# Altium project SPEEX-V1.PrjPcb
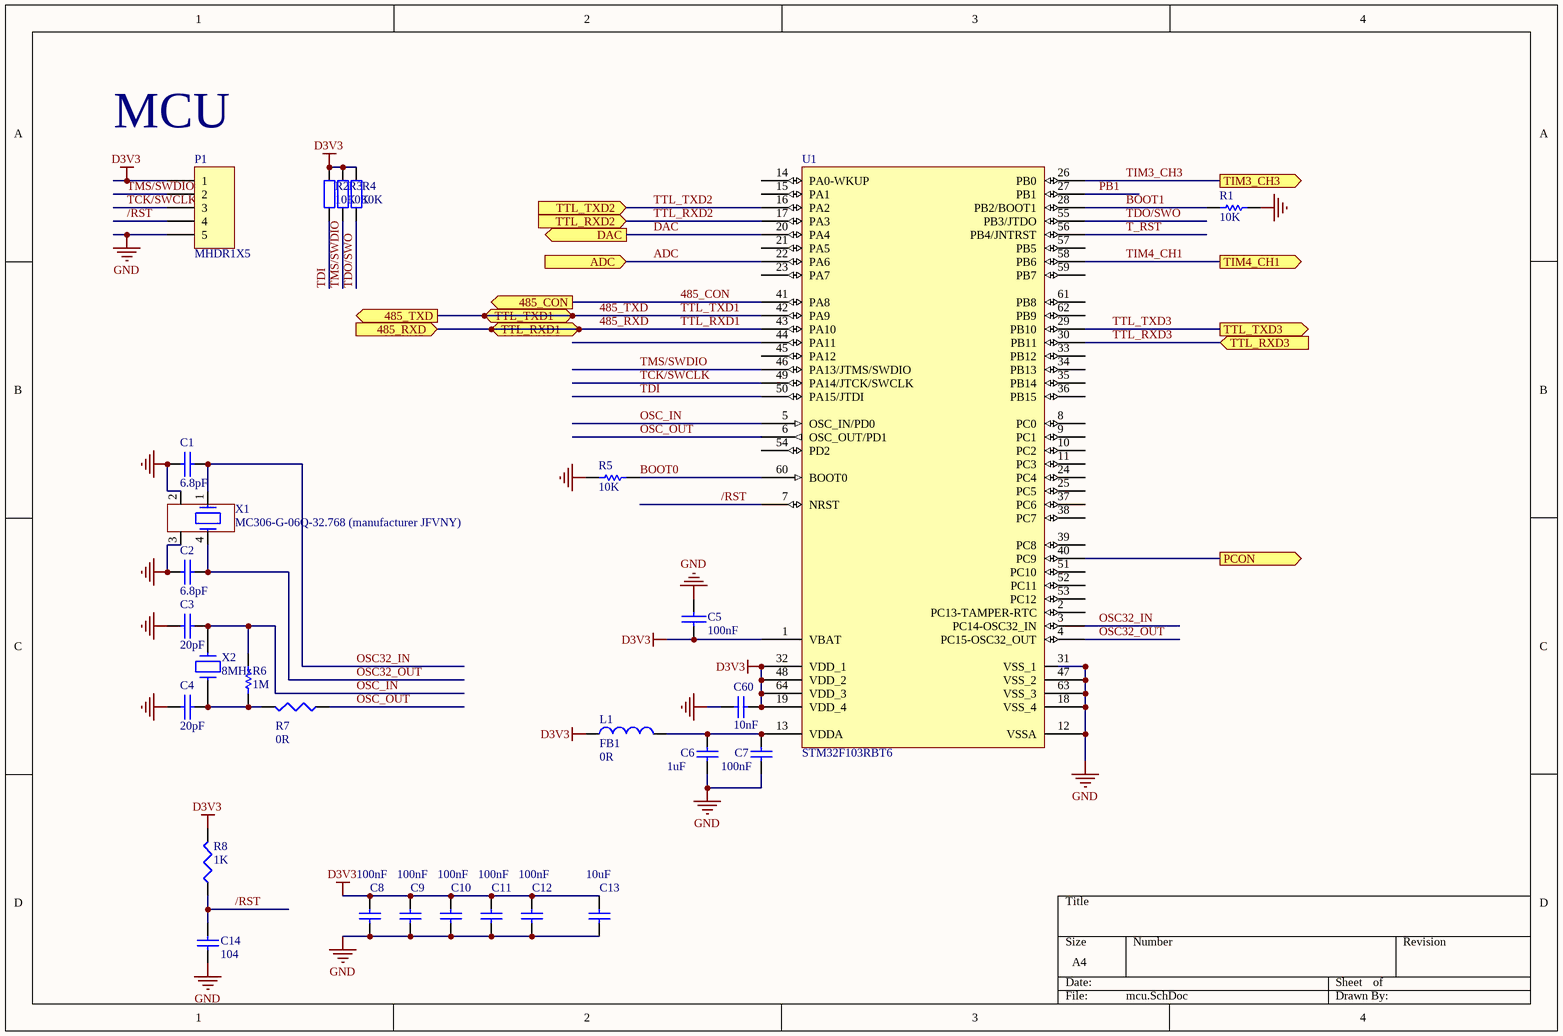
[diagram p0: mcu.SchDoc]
4 sheets, 127 parts. Net scope: flat (ports and power ports of the same name join across sheets).
Board file: SPEEX-V1.PcbDoc
Sheets:
  mcu.SchDoc
  audio_inout.SchDoc
  rs232_485.SchDoc
  power.SchDoc

## Sheet mcu.SchDoc
size A4

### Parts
C1  6.8pF  [C-0603]
C2  6.8pF  [C-0603]
C3  20pF  [C-0603]
C4  20pF  [C-0603]
C5  100nF  [C-0603]
C6  1uF  [C-0603]
C7  100nF  [C-0603]
C8  100nF  [C-0603]
C9  100nF  [C-0603]
C10  100nF  [C-0603]
C11  100nF  [C-0603]
C12  100nF  [C-0603]
C13  10uF  [C-0603]
C14  104  [C-0603]
C60  10nF  [C0603]
L1  FB1  value 0R  [R-0805]
P1  MHDR1X5  [HDR1X5]
R1  10K  [R0603]
R2  10K  [R-0603]
R3  10K  [R-0603]
R4  10K  [R-0603]
R5  10K  [R-0603]
R6  1M  [R-0603]
R7  0R  [R-0603]
R8  1K  [R-0603]
U1  STM32F103RBT6  [LQFP64_N]
X1  MC306-G-06Q-32.768 (manufacturer JFVNY)  [32.768K-MC146]
X2  8MHz  [XTAL-CJ]

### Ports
485_CON (out), 485_RXD (in), 485_TXD (out), ADC (in), DAC (out), PCON (out), TIM3_CH3 (out), TIM4_CH1 (out), TTL_RXD1 (in), TTL_RXD2 (in), TTL_RXD3 (in), TTL_TXD1 (out), TTL_TXD2 (in), TTL_TXD3 (out)

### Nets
D3V3: C5.2 C8.2 C9.2 C10.2 C11.2 C12.2 C13.2 C60.2 L1.1 P1.1 R2.1 R3.1 R4.1 R8.2 U1.1(VBAT) U1.19(VDD_4) U1.32(VDD_1) U1.48(VDD_2) U1.64(VDD_3)
GND: C1.2 C2.2 C3.2 C4.2 C5.1 C6.1 C7.1 C8.1 C9.1 C10.1 C11.1 C12.1 C13.1 C14.1 C60.1 P1.5 R1.2 R5.2 U1.12(VSSA) U1.18(VSS_4) U1.31(VSS_1) U1.47(VSS_2) U1.63(VSS_3) X1.2 X1.3
485_CON: U1.41(PA8) ; port 485_CON
485_RXD: U1.43(PA10) ; port TTL_RXD1, port 485_RXD  [also labelled TTL_RXD1]
485_TXD: U1.42(PA9) ; port TTL_TXD1, port 485_TXD  [also labelled TTL_TXD1]
/RST: C14.2 P1.4 R8.1 U1.7(NRST)
ADC: U1.22(PA6) ; port ADC
BOOT0: R5.1 U1.60(BOOT0)
BOOT1: R1.1 U1.28(PB2/BOOT1)
DAC: U1.20(PA4) ; port DAC
OSC32_IN: C1.1 U1.3(PC14-OSC32_IN) X1.1
OSC32_OUT: C2.1 U1.4(PC15-OSC32_OUT) X1.4
OSC_IN: C3.1 R6.2 U1.5(OSC_IN/PD0) X2.1
OSC_OUT: R7.1 U1.6(OSC_OUT/PD1)
PB1: U1.27(PB1)
PCON: U1.40(PC9) ; port PCON
T_RST: U1.56(PB4/JNTRST)
TCK/SWCLK: P1.3 U1.49(PA14/JTCK/SWCLK)
TDI: R2.2 U1.50(PA15/JTDI)
TDO/SWO: R4.2 U1.55(PB3/JTDO)
TIM3_CH3: U1.26(PB0) ; port TIM3_CH3
TIM4_CH1: U1.58(PB6) ; port TIM4_CH1
TMS/SWDIO: P1.2 R3.2 U1.46(PA13/JTMS/SWDIO)
TTL_RXD2: U1.17(PA3) ; port TTL_RXD2
TTL_RXD3: U1.30(PB11) ; port TTL_RXD3
TTL_TXD2: U1.16(PA2) ; port TTL_TXD2
TTL_TXD3: U1.29(PB10) ; port TTL_TXD3
NetC4_1: C4.1 R6.1 R7.2 X2.2
NetC6_2: C6.2 C7.2 L1.2 U1.13(VDDA)

Not connected (* = marked no-connect by the designer): U1 2(PC13-TAMPER-RTC) 8(PC0) 9(PC1) 10(PC2) 11(PC3) 14(PA0-WKUP) 15(PA1) 21(PA5) 23(PA7) 24(PC4) 25(PC5) 33(PB12) 34(PB13) 35(PB14) 36(PB15) 37(PC6) 38(PC7) 39(PC8) 44(PA11) 45(PA12) 51(PC10) 52(PC11) 53(PC12) 54(PD2) 57(PB5) 59(PB7) 61(PB8) 62(PB9)

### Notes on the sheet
- (near P1) MCU

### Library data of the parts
C1-C5 = CAP: Capacitor
C6-C14 = Cap: Capacitor; Value: 100pF
C60 = Cap: Capacitor
L1 = Inductor: Code_IEC: 1005
P1 = MHDR1X5: Header, 5-Pin
R1 R5 R6 = res1: Resistor; Value: 1K
R2-R4 = RES
R7 = Res3: Resistor; Value: 1K
R8 = Res3: Resistor
U1 = STM32F103RBT6: STM32 ARM-based 32-bit MCU with 128 Kbytes Flash, 64-pin LQFP, Industrial Temperature
X1 = MC306
X2 = CRYSTAL

## Sheet audio_inout.SchDoc
size A4
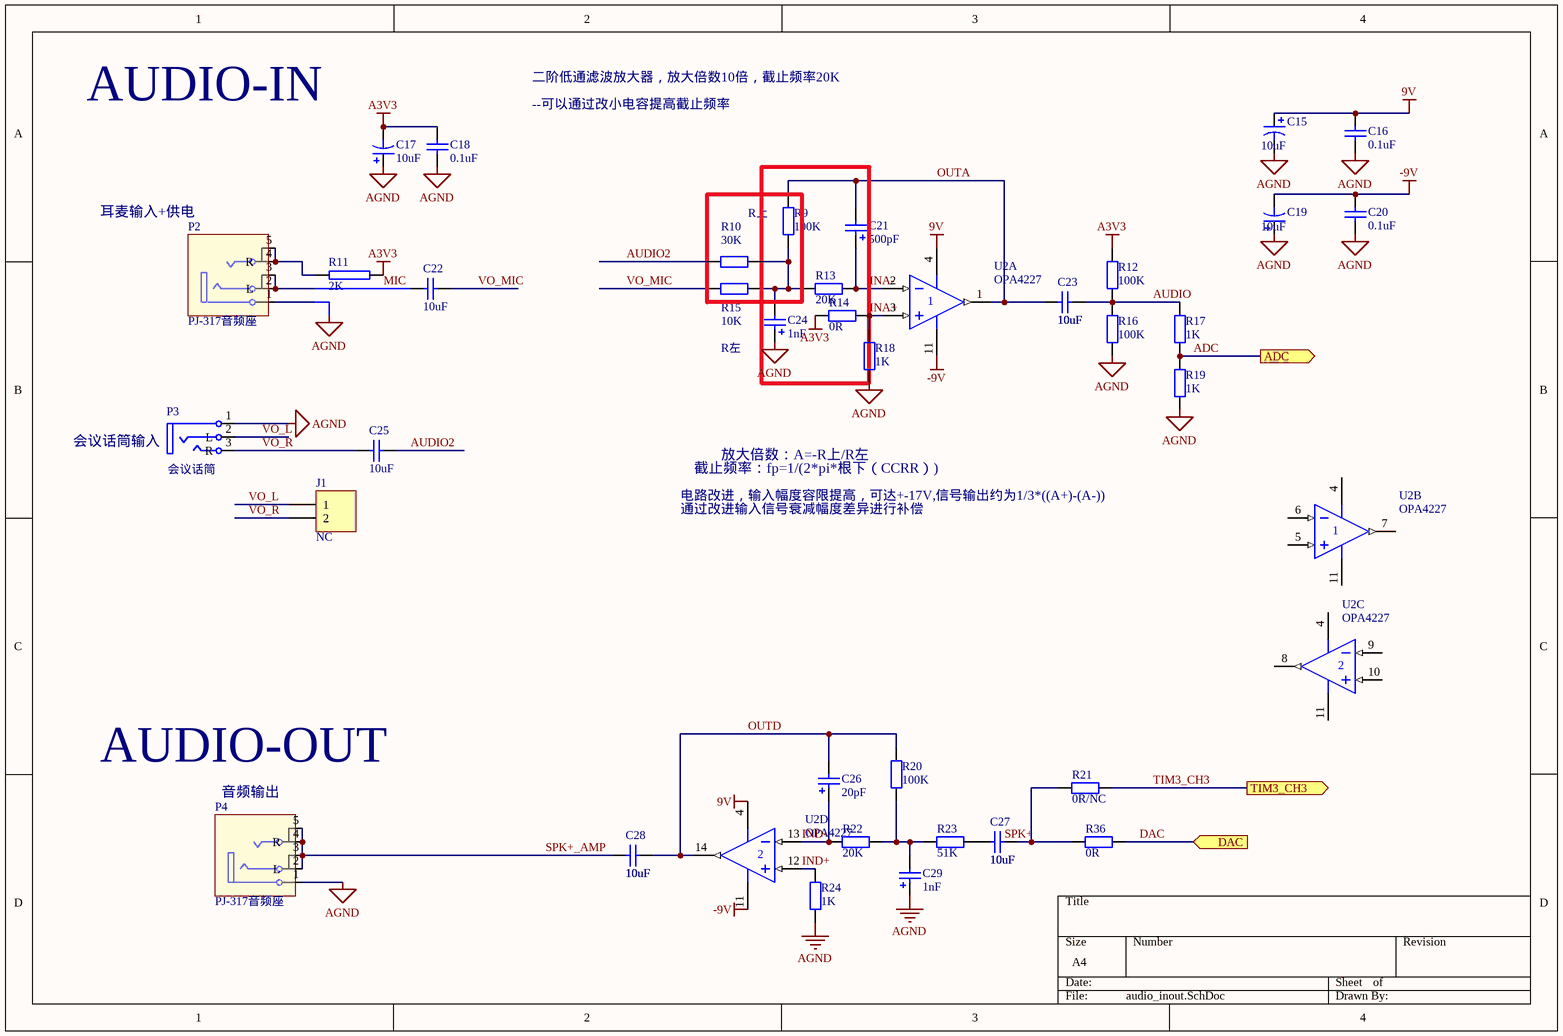
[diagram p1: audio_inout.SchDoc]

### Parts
C15  10uF  [C-0805]
C16  0.1uF  [C-0603]
C17  10uF  [C0805]
C18  0.1uF  [C-0603]
C19  10uF  [C-0805]
C20  0.1uF  [C-0603]
C21  500pF  [C-0603]
C22  10uF  [C-0603]
C23  10uF  [C-0603]
C24  1nF  [C-0603]
C25  10uF  [C-0603]
C26  20pF  [C-0603]
C27  10uF  [C-0603]
C28  10uF  [C-0603]
C29  1nF  [C-0603]
J1  NC  [CON_PAD2]
P2  PJ-317音频座  [PJ-317]
P3  会议话筒  [PJ-603(A)-2]
P4  PJ-317音频座  [PJ-317]
R9  100K  [R-0603]
R10  30K  [R-0603]
R11  2K  [R-0603]
R12  100K  [R-0603]
R13  20K  [R-0603]
R14  0R  [R-0603]
R15  10K  [R-0603]
R16  100K  [R-0603]
R17  1K  [R-0603]
R18  1K  [R-0603]
R19  1K  [R-0603]
R20  100K  [R-0603]
R21  0R/NC  [R-0603]
R22  20K  [R-0603]
R23  51K  [R-0603]
R24  1K  [R-0603]
R36  0R  [R-0603]
U2  OPA4227  [D014_L]  (parts A,B,C,D of 4)

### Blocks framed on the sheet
R上: R9 R10 R15

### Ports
ADC (out), DAC (in), TIM3_CH3 (out)

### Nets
9V: C15.1 C16.2 U2.4(V+)
-9V: C19.2 C20.2 U2.11(V-)
A3V3: C17.2 C18.2 R11.1 R12.1 R14.1
AGND: C15.2 C16.1 C17.1 C18.1 C19.1 C20.1 C24.1 C29.1 P2.1(S) P3.1(S) P4.1(S) R16.2 R18.2 R19.2 R24.2
ADC: R17.2 R19.1 ; port ADC
AUDIO: C23.1 R12.2 R16.1 R17.1
AUDIO2: C25.2 R10.1
DAC: R36.1 ; port DAC
INA+: R14.2 R18.1 U2.3(IN+)
INA-: C21.1 R13.1 U2.2(IN-)
IND+: R24.1 U2.12(IN+)
IND-: C26.1 R22.1 U2.13(IN-)
MIC: C22.1 P2.2(L) P2.3(L)
OUTA: C21.2 C23.2 R9.2 U2.1(OUT)
OUTD: C26.2 C28.1 R20.2 U2.14(OUT)
SPK+_AMP: C28.2 P4.2(L) P4.3(L) P4.4(R) P4.5(R)
TIM3_CH3: R21.1 ; port TIM3_CH3
VO_L: J1.1 P3.2(L)
VO_MIC: C22.2 R15.1
VO_R: C25.1 J1.2 P3.3(R)
NetC24_2: C24.2 R9.1 R10.2 R13.2 R15.2
NetC27_1: C27.1 R21.2 R36.2
NetC27_2: C27.2 R23.1
NetC29_2: C29.2 R20.1 R22.2 R23.2
NetP2_4: P2.4(R) P2.5(R) R11.2

Not connected (* = marked no-connect by the designer): U2 5(IN+) 6(IN-) 7(OUT) 8(OUT) 9(IN-) 10(IN+)

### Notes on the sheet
- AUDIO-IN
- 二阶低通滤波放大器，放大倍数10倍，截止频率20K
- --可以通过改小电容提高截止频率
- 耳麦输入+供电
- R左
- 会议话筒输入
- 电路改进，输入幅度容限提高，可达+-17V,信号输出约为1/3*((A+)-(A-))
- 通过改进输入信号衰减幅度差异进行补偿
- 截止频率：fp=1/(2*pi*根下（CCRR）)
- 放大倍数：A=-R上/R左
- AUDIO-OUT
- (near P4) 音频输出
- Labels drawn without touching a wire or pin: SPK+

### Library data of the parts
C15 C17 C19 = Cap Pol1: Polarized Capacitor (Radial)
C16 C18 C20 C22 C23 C25 C27 C28 = CAP
C21 C24 C26 C29 = Cap Pol2: Polarized Capacitor (Axial); Value: 100pF
J1 = Header 2: Header, 2-Pin
P2 P4 = PJ-317
P3 = MIC
R9 R10 R12-R24 R36 = RES
R11 = RES2

## Sheet rs232_485.SchDoc
size A4
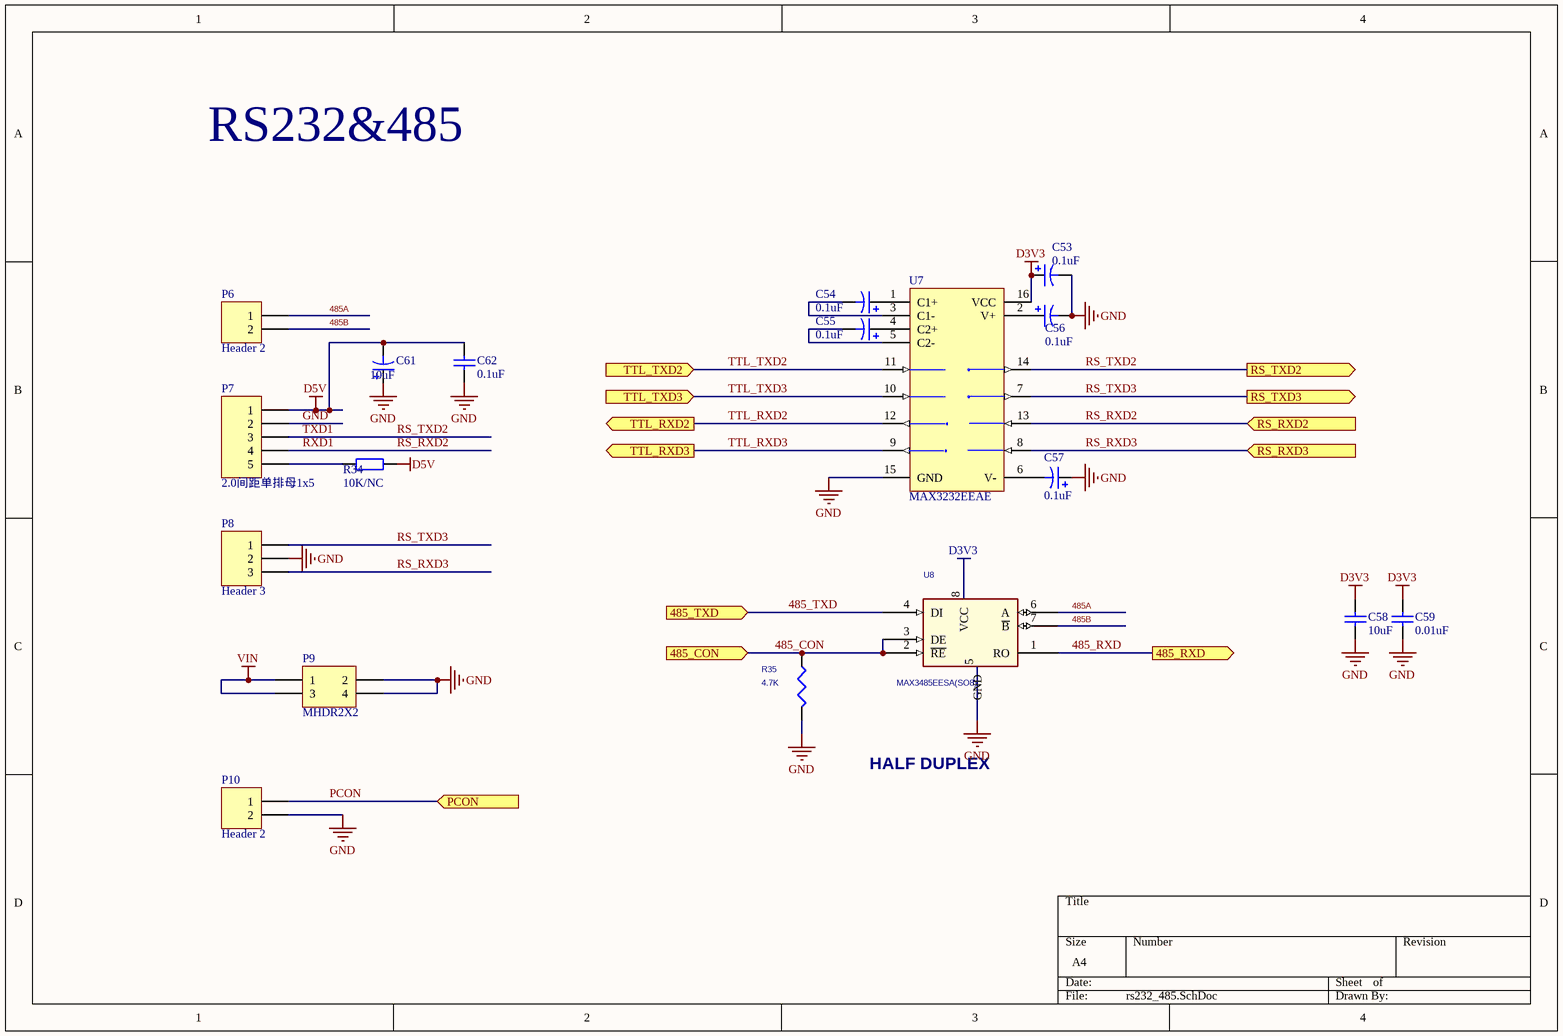
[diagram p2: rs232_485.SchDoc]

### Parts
C53  0.1uF  [C-0603]
C54  0.1uF  [C-0603]
C55  0.1uF  [C-0603]
C56  0.1uF  [C-0603]
C57  0.1uF  [C-0603]
C58  10uF  [C-0603]
C59  0.01uF  [C-0603]
C61  10uF  [C-0805]
C62  0.1uF  [C-0603]
P6  Header 2  [HDR1X2]
P7  2.0间距单排母1x5  [pin5]
P8  Header 3  [HDR1X3]
P9  MHDR2X2  [HDR2X2]
P10  Header 2  [HDR1X2]
R34  10K/NC  [R-0603]
R35  4.7K  [R-0603]
U7  MAX3232EEAE  [SSOP16]
U8  MAX3485EESA(SO8)  [SO8]

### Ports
485_CON (in), 485_RXD (out), 485_TXD (in), PCON (in), RS_RXD2 (in), RS_RXD3 (in), RS_TXD2 (out), RS_TXD3 (out), TTL_RXD2 (out), TTL_RXD3 (out), TTL_TXD2 (in), TTL_TXD3 (in)

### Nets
D3V3: C53.1 C58.1 C59.1 U7.16(VCC) U8.8(VCC)  [also labelled VCC]
D5V: C61.2 C62.2 P7.1 R34.2
GND: C53.2 C56.2 C57.1 C58.2 C59.2 C61.1 C62.1 P7.2 P8.2 P9.2 P9.4 P10.2 R35.2 U7.15(GND) U8.5(GND)
VIN: P9.1 P9.3
485_CON: R35.1 U8.2(~{RE}) U8.3(DE) ; port 485_CON
485_RXD: U8.1(RO) ; port 485_RXD
485_TXD: U8.4(DI) ; port 485_TXD
485A: P6.1 U8.6(A)
485B: P6.2 U8.7(~{B})
PCON: P10.1 ; port PCON
RS_RXD2: P7.4 U7.13(R1IN) ; port RS_RXD2  [also labelled RXD1]
RS_RXD3: P8.3 U7.8(R2IN) ; port RS_RXD3
RS_TXD2: P7.3 U7.14(T1OUT) ; port RS_TXD2  [also labelled TXD1]
RS_TXD3: P8.1 U7.7(T2OUT) ; port RS_TXD3
TTL_RXD2: U7.12(R1OUT) ; port TTL_RXD2
TTL_RXD3: U7.9(R2OUT) ; port TTL_RXD3
TTL_TXD2: U7.11(T1IN) ; port TTL_TXD2
TTL_TXD3: U7.10(T2IN) ; port TTL_TXD3
NetC54_1: C54.1 U7.1(C1+)
NetC54_2: C54.2 U7.3(C1-)
NetC55_1: C55.1 U7.4(C2+)
NetC55_2: C55.2 U7.5(C2-)
NetC56_1: C56.1 U7.2(V+)
NetC57_2: C57.2 U7.6(V-)
NetP7_5: P7.5 R34.1

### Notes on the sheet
- RS232&485
- HALF DUPLEX

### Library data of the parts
C53-C57 C61 = Cap Pol1: Polarized Capacitor (Radial)
C58 C59 = Cap: Capacitor
C62 = CAP
P6 P10 = Header 2: Header, 2-Pin
P7 = Header 5: Header, 5-Pin
P8 = Header 3: Header, 3-Pin
P9 = MHDR2X2: Header, 2-Pin, Dual row
R34 = Res2: Resistor; Value: 1K
R35 = RESISTOR_Dup1: RES,5%,1/10W,SMD0603; Part Code: B15G-114-547255-00; Part Code (2): B15G-114-247235-00; PCMCIA Interface: PCMCIA; FDF: Common Interface - PCMCIA Card Reader - Glue - 1; Assembly: Discrete smd - top
U7 = MAX3232EEAE: ?5kV ESD-Protected, 3.0V to 5.5V, Low-Power, up to 250kbps, True RS-232 Transceiver
U8 = MAX485E

## Sheet power.SchDoc
size A4
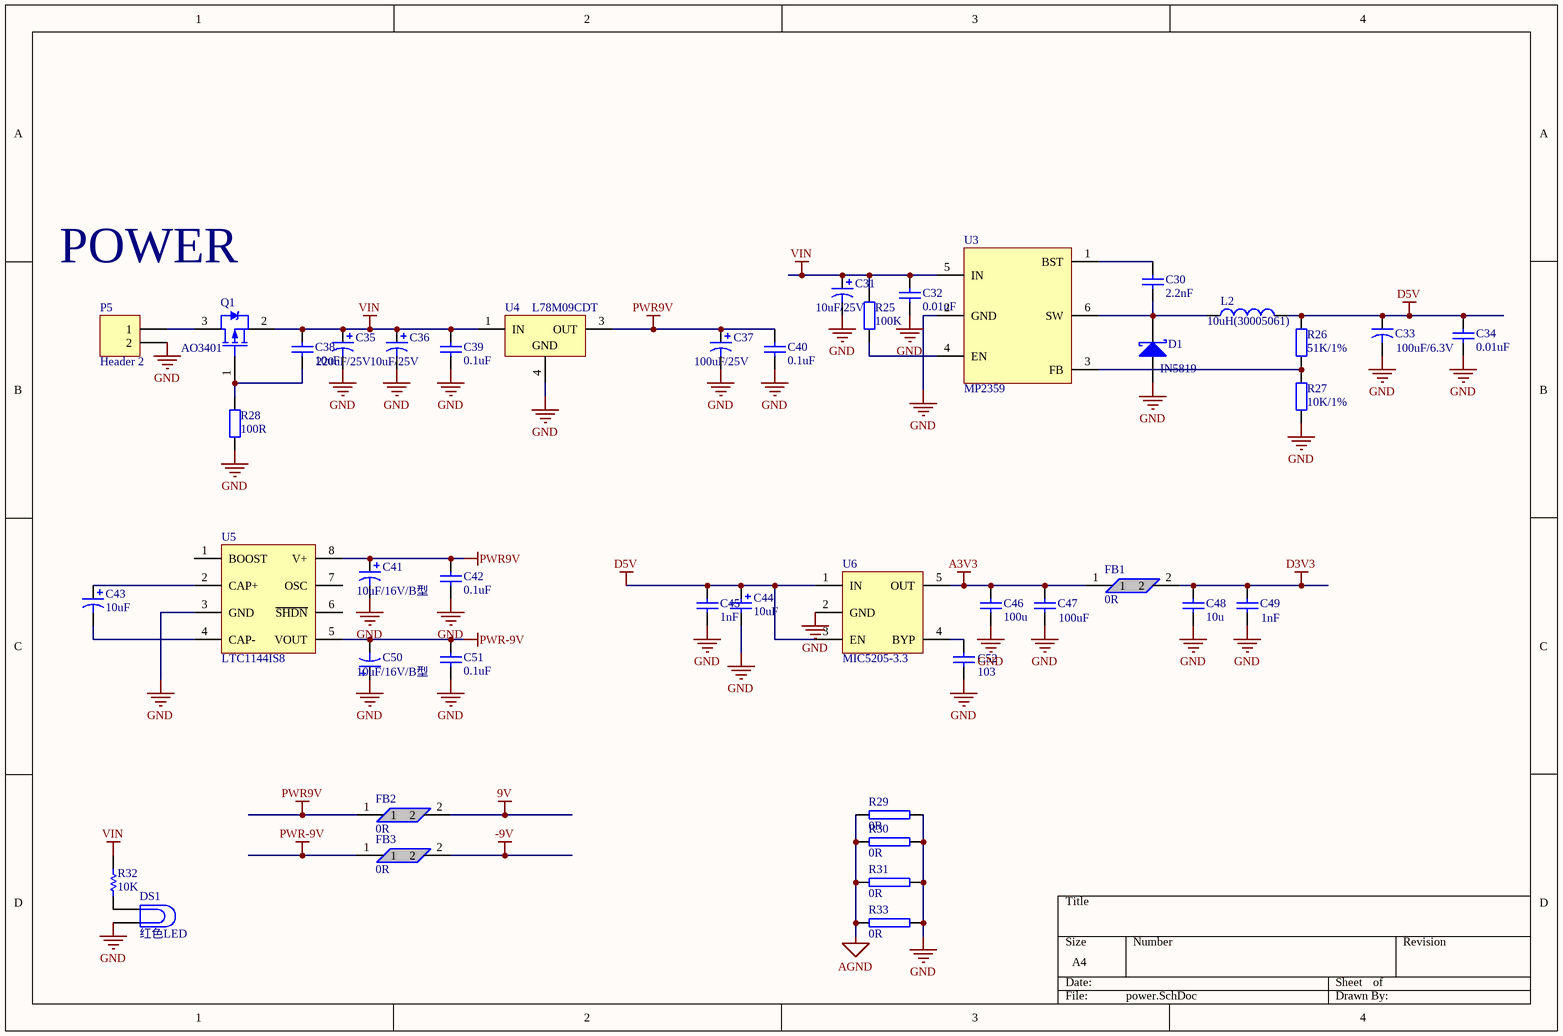
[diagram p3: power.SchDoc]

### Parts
C30  2.2nF  [C-0603]
C31  10uF/25V  [C-1210]
C32  0.01uF  [C-0603]
C33  100uF/6.3V  [C-1210]
C34  0.01uF  [C-0603]
C35  220uF/25V  [ECAP_SMD_8.5MM]
C36  10uF/25V  [C-1210]
C37  100uF/25V  [CAP]
C38  10uF  [C-0603]
C39  0.1uF  [C-0603]
C40  0.1uF  [C-0603]
C41  10uF/16V/B型  [C-1210]
C42  0.1uF  [C-0603]
C43  10uF  [CAP0.5]
C44  10uF  [C0805]
C45  1nF  [C-0603]
C46  100u  [C-0603]
C47  100uF  [C-0603]
C48  10u  [C-0603]
C49  1nF  [C-0603]
C50  10uF/16V/B型  [C-1210]
C51  0.1uF  [C-0603]
C52  103  [C-0603]
D1  IN5819  [SMB]
DS1  红色LED  [Led-0603]
FB1  0R  [R-0805]
FB2  0R  [R-0805]
FB3  0R  [R-0805]
L2  10uH(30005061)  [C2225]
P5  Header 2  [HDR1X2]
Q1  AO3401  [SOT23A]
R25  100K  [R-0603]
R26  51K/1%  [R-0603]
R27  10K/1%  [R-0603]
R28  100R  [R-0603]
R29  0R  [R-0603]
R30  0R  [R-0603]
R31  0R  [R-0603]
R32  10K  [R-0603]
R33  0R  [R-0603]
U3  MP2359  [SOT23-6]
U4  L78M09CDT  [TO-252]
U5  LTC1144IS8  [SO-8]
U6  MIC5205-3.3  [SOT23-5]

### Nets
9V: FB2.2
-9V: FB3.2
A3V3: C46.1 C47.1 FB1.1 U6.5(OUT)
AGND: R29.1 R30.1 R31.1 R33.1
D3V3: C48.1 C49.1 FB1.2
D5V: C33.1 C34.2 C44.1 C45.1 L2.2 R26.1 U6.1(IN) U6.3(EN)
GND: C31.2 C32.1 C33.2 C34.1 C35.2 C36.2 C37.2 C39.1 C40.1 C41.2 C42.1 C44.2 C45.2 C46.2 C47.2 C48.2 C49.2 C50.1 C51.1 C52.2 D1.1(A) DS1.2 P5.2 R27.2 R28.2 R29.2 R30.2 R31.2 R33.2 U3.2(GND) U4.4(GND) U5.3(GND) U6.2(GND)
PWR9V: C37.1 C40.2 C41.1 C42.2 FB2.1 U4.3(OUT) U5.8(V+)
PWR-9V: C50.2 C51.2 FB3.1 U5.5(VOUT)
VIN: C31.1 C32.2 C35.1 C36.1 C38.2 C39.2 Q1.2(S) R25.1 R32.1 U3.5(IN) U4.1(IN)
NetC30_1: C30.1 U3.1(BST)
NetC30_2: C30.2 D1.2(K) L2.1 U3.6(SW)
NetC38_1: C38.1 Q1.1(G) R28.1
NetC43_1: C43.1 U5.2(CAP+)
NetC43_2: C43.2 U5.4(CAP-)
NetC52_1: C52.1 U6.4(BYP)
NetDS1_1: DS1.1 R32.2
NetP5_1: P5.1 Q1.3(D)
NetR25_2: R25.2 U3.4(EN)
NetR26_2: R26.2 R27.1 U3.3(FB)

Not connected (* = marked no-connect by the designer): U5 1(BOOST) 6(~{SHDN}) 7(OSC)

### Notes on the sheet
- POWER

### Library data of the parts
C30 C32 C34 C38 C45 C48 C49 C52 = Cap: Capacitor
C31 C35-C37 C41 C43 C50 = Cap Pol1: Polarized Capacitor (Radial)
C33 = Cap2: Capacitor
C39 C40 C42 C51 = CAP
C44 = Cap Pol3: Polarized Capacitor (Surface Mount); Value: 100pF
C46 = Cap: Capacitor; Value: 10u
C47 = Cap: Capacitor; Value: 1nF
D1 = D Schottky: Schottky Diode
DS1 = Lamp: Incandescent Bulb
FB1-FB3 = FB
L2 = Inductor: Code_IEC: 1005; Value: 7.2uH
P5 = Header 2: Header, 2-Pin
R25-R28 = Res2: Resistor; Value: 1K
R29-R31 R33 = RES2
R32 = Res Semi: Semiconductor Resistor; Value: 1K
U4 = L78M09CDT: Positive Voltage Regulator
U6 = MIC5205: 800mA Low Dropout Positive Regulator Fixed 2.85V,3V,3.3V and 5V; PackageDocument: revC

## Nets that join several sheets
9V: audio_inout (C15.1 C16.2 U2.4), power (FB2.2)
-9V: audio_inout (C19.2 C20.2 U2.11), power (FB3.2)
A3V3: audio_inout (5 pins), power (C46.1 C47.1 FB1.1 U6.5)
AGND: audio_inout (15 pins), power (R29.1 R30.1 R31.1 R33.1)
D3V3: mcu (19 pins), rs232_485 (5 pins), power (C48.1 C49.1 FB1.2)
D5V: rs232_485 (C61.2 C62.2 P7.1 R34.2), power (8 pins)
GND: mcu (25 pins), rs232_485 (15 pins), power (33 pins)
VIN: rs232_485 (P9.1 P9.3), power (11 pins)
485_CON: mcu (U1.41), rs232_485 (R35.1 U8.2 U8.3)
485_RXD: mcu (U1.43), rs232_485 (U8.1)
485_TXD: mcu (U1.42), rs232_485 (U8.4)
ADC: mcu (U1.22), audio_inout (R17.2 R19.1)
DAC: mcu (U1.20), audio_inout (R36.1)
PCON: mcu (U1.40), rs232_485 (P10.1)
TIM3_CH3: mcu (U1.26), audio_inout (R21.1)
TTL_RXD2: mcu (U1.17), rs232_485 (U7.12)
TTL_RXD3: mcu (U1.30), rs232_485 (U7.9)
TTL_TXD2: mcu (U1.16), rs232_485 (U7.11)
TTL_TXD3: mcu (U1.29), rs232_485 (U7.10)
